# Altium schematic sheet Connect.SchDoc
size A4
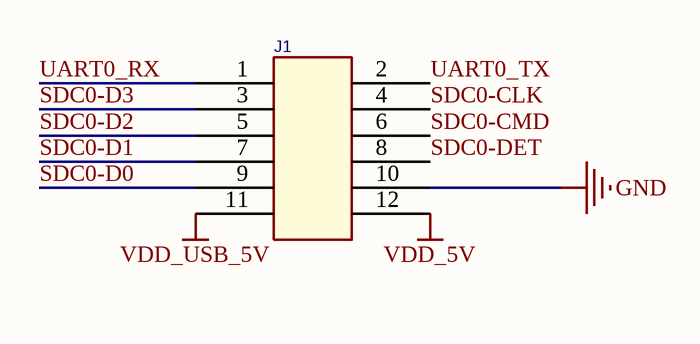
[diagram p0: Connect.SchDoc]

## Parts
J1  MIPI0  [TEST_CORE]  (value not drawn)

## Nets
GND: J1.10
VDD_5V: J1.12
VDD_USB_5V: J1.11
SDC0-CLK: J1.4
SDC0-CMD: J1.6
SDC0-D0: J1.9
SDC0-D1: J1.7
SDC0-D2: J1.5
SDC0-D3: J1.3
SDC0-DET: J1.8
UART0_RX: J1.1
UART0_TX: J1.2

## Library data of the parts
J1 = TEST_12P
